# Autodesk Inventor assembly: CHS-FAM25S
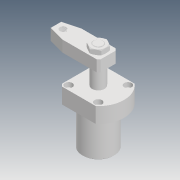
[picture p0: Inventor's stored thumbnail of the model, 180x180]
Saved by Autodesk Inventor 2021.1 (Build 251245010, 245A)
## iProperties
Created: 2019-04
Part Number: CHS-FAM25S
Description: STEP AP203
Document SubType Name: Assembly
Designer: user
Title: chs-fam25s_asm.STEP
Revision Number: ÈÎºÎ
Sending System: SolidWorks 2017
Preprocessor: SwSTEP 2.0
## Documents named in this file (5)
- D:\Vault_2016\Projekty\Clamptek\Hydraulic\CHS\CHS-25\Inventor\CHS-FAM25S\CHS-FAM25S.iam
- D:\Vault_2016\Projekty\Clamptek\Hydraulic\CHS\CHS-25\Inventor\CHS-FAM25S\CHS-FAM25BT.ipt
- D:\Vault_2016\Projekty\Clamptek\Hydraulic\CHS\CHS-25\Inventor\CHS-FAM25S\CHS-25S-02_1.ipt
- D:\Vault_2016\Projekty\Clamptek\Hydraulic\CHS\CHS-25\Inventor\CHS-FAM25S\CHS-25S-01_1.ipt
- D:\Vault_2016\Projekty\Clamptek\Hydraulic\CHS\CHS-25\Inventor\CHS-FAM25S\M14_1.ipt
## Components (4 placed, 4 different names)
1. CHS-FAM25BT_1
2. CHS-25S-02_1_2
3. CHS-25S-01_1_3
4. M14_1_4
